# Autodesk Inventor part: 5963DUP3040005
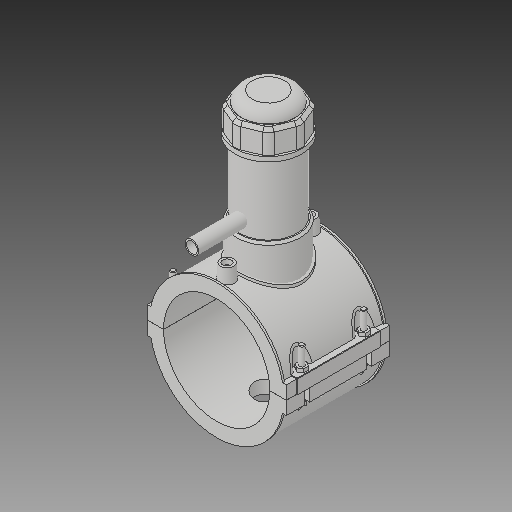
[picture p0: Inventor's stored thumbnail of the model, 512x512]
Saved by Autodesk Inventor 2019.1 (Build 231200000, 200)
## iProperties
Created: 2017-07
Part Number: 5963DUP3040005
Material: Generic
Description: PLASSON TAPPING SADDLE 4''DIPS x 1/2''CTS
Document SubType Name: Modeling
Designer: KIM
Density: 1 g/cm^3
Appearance: Default
Author: KIM
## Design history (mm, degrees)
derived "5963DBP_5963BUP.ipt"
feature "Solid1::5963DBP_5963BUP.ipt"
feature "Solid2::5963DBP_5963BUP.ipt"
feature "Solid3::5963DBP_5963BUP.ipt"
tag "TaggingFeature1"
body "Solid1"
body "Solid2"
body "Solid3"
other parameters: "d0" = 121.3, "d2" = 159.004, "d3" = 30.325, "d4" = 118.11, "d5" = 0, "d6" = 0.1, "d8" = 0, "d19" = 6, "d20" = 6, "d21" = 70.866, "d23" = 0, "d24" = 35.433, "d26" = 0, "d27" = 3, "d28" = 3, "d29" = 3, "d30" = 40.43333, "d31" = 6, "d32" = 0, "d33" = 0, "d34" = 0.6, "d40" = 78.21424, "d41" = 76.419, "d43" = 0, "d45" = 0, "d47" = 146.072, "d70" = 15, "d72" = 0, "d73" = 6, "d75" = 5, "d76" = 0, "d77" = 6.065, "d78" = 90.65, "d79" = 15, "d80" = 47.244, "d82" = 5 deg, "d84" = 4, "d85" = 14, "d86" = 0, "d87" = 3, "d88" = 0, "d89" = 1, "d90" = 1, "d91" = 94.488, "d92" = 0, "d93" = 0.5, "d94" = 63.84211, "d96" = 153.42024, "d97" = 2.3622, "d98" = 0, "d120" = 140 deg, "d121" = 24.228, "d122" = 20 deg, "d123" = 300.824, "d124" = 90.2472, "d126" = 0, "d143" = 124.939, "d145" = 22.39385, "d149" = 1.8195, "d150" = 24.63323, "d153" = 118.11, "d154" = 0, "d156" = 75.206, "d157" = 160 deg, "d159" = 5.8224, "d161" = 1.8195, "d162" = 70.866, "d163" = 0, "d164" = 60.65, "d167" = 12.13, "d168" = 73.37171, "d170" = 3.4335, "d172" = 0, "d173" = 1, "d175" = 60.65, "d176" = 20 deg, "d177" = 8.491, "d178" = 29.112, "d180" = 0, "d183" = 11.6448, "d184" = 6.7928, "d185" = 38.38575, "d186" = 38.38575, "d187" = 75.206, "d188" = 8.7336, "d189" = 8.491, "d190" = 0, "d191" = 112.809, "d193" = 7.3248, "d194" = 4.13385, "d195" = 90 deg, "d197" = 0, "d199" = 0, "d200" = 14.556, "d202" = 0, "d203" = 177.038, "d204" = 72.59805, "d205" = 53.4933, "d206" = 64.95615, "d207" = 132.7785, "d208" = 138.08964, "d209" = 164.64534, "d210" = 65.72034, "d211" = 76.419, "d212" = 61.1352, "d213" = 51.4116, "d216" = 0, "d217" = 12.13, "d218" = 12.13, "d219" = 2.426, "d222" = 121.3, "d224" = 0, "d225" = 65.024, "d226" = 15.8, "d227" = 12.64, "d228" = 87.376, "d230" = 3.639, "d_" = 121.3, "B_" = 159.004, "L_" = 118.11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
